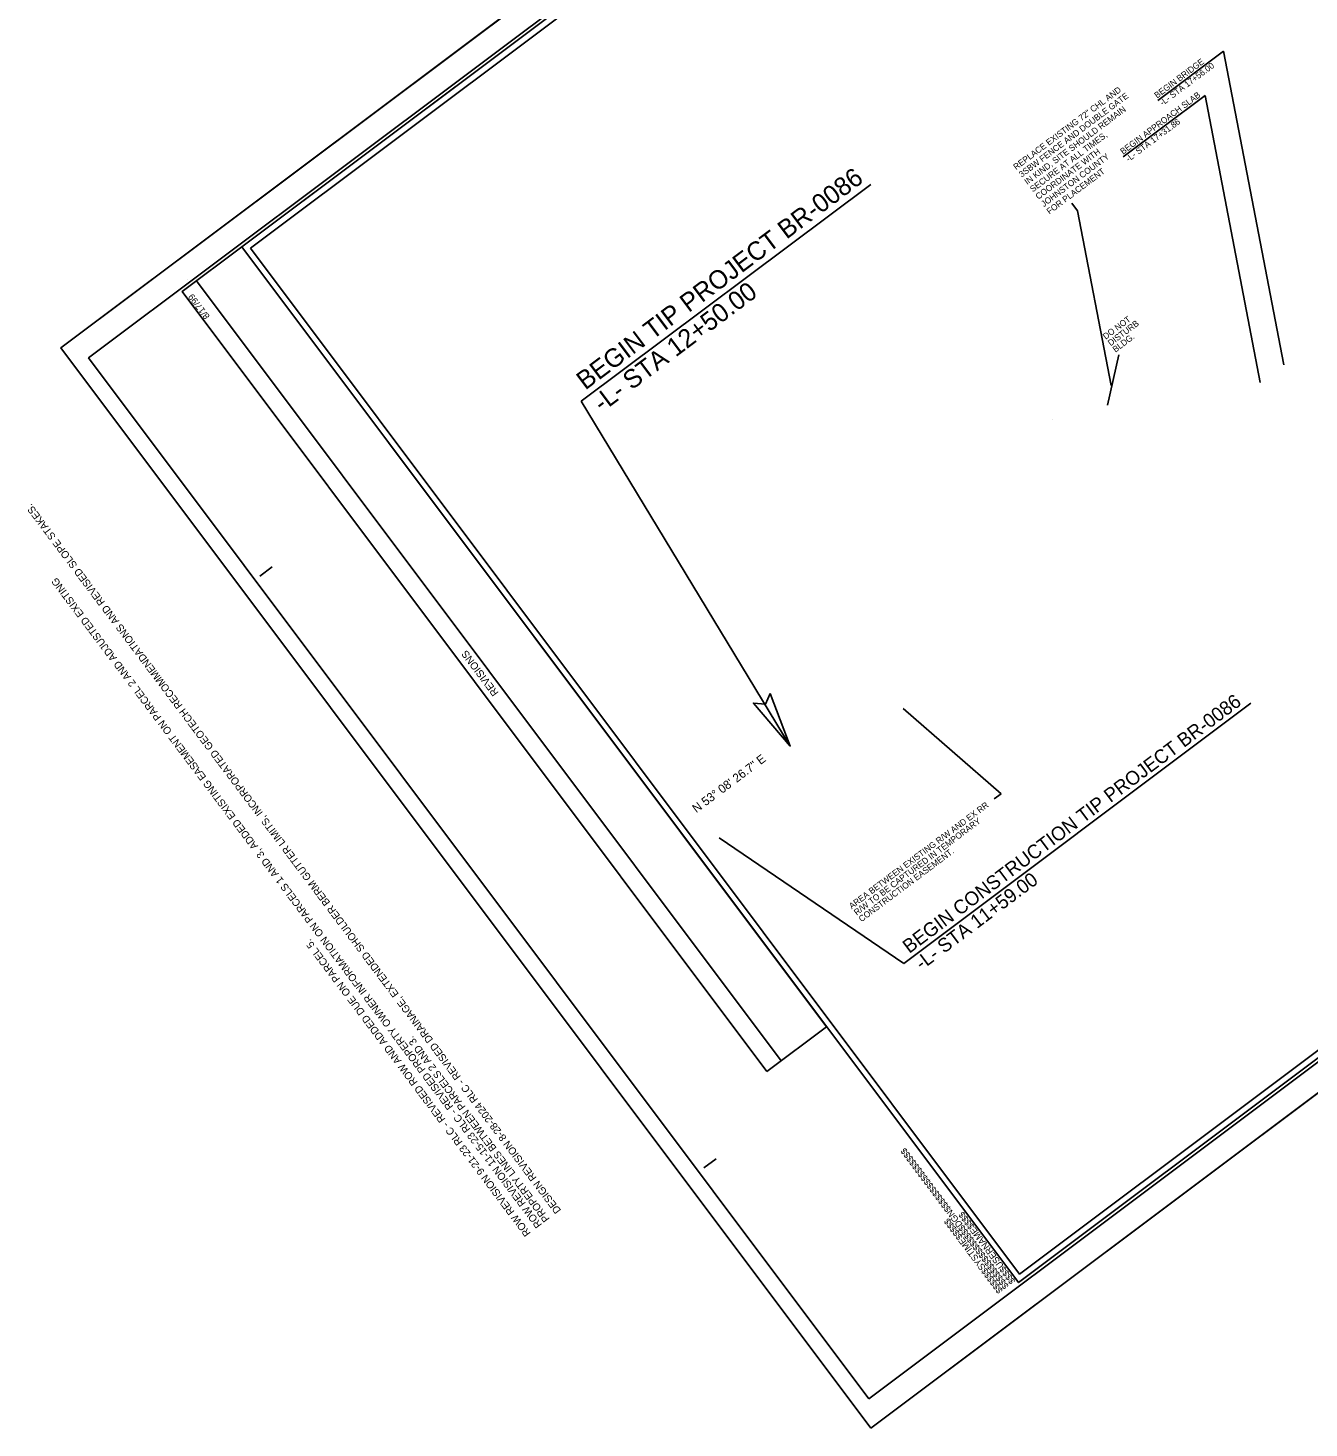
# Model space of a CAD drawing. Extents: x 2186558 to 2188589, y 629855 to 631741.
# Drawn here: x 2186558 to 2187597, y 629855 to 630990 of the extents above; entities that cross this region are included whole.
import ezdxf

# ---------------------------------------------------------------- set-up
doc = ezdxf.new("R2010")
doc.units = 0
for name, color, linetype in [('Prop Dimension', 7, 'Continuous'), ('Prop Dimension Text', 7, 'Continuous'), ('Prop Horizontal Alignment Direction Label', 7, 'Continuous'), ('Prop Terminator CELL', 7, 'Continuous'), ('Scratch_Level_0', 7, 'Continuous'), ('Scratch_Level_8', 7, 'Continuous'), ('Sheet Block Revision CELL', 7, 'Continuous'), ('Sheet Cutting Line CELL', 7, 'Continuous'), ('Sheet Plan CELL', 7, 'Continuous'), ('Sheet Plan Layout CELL', 7, 'Continuous'), ('Sheet Plot Border Inside CELL', 7, 'Continuous'), ('Sheet Plot Border Outside CELL', 7, 'Continuous')]:
    doc.layers.add(name, color=color, linetype=linetype)

msp = doc.modelspace()

# ---------------------------------------------------------------- linework, layer by layer
at = {"layer": 'Prop Dimension'}
for p, q in [((2187474.6, 630931.7), (2187527.8, 630971.6)), ((2187576.9, 630717.4), (2187527.8, 630971.6)), ((2187446.5, 630885.9), (2187513.1, 630935.8)), ((2187557.6, 630702.9), (2187513.1, 630935.8)), ((2187007, 630687.8), (2187241.7, 630863.7)), ((2187409.4, 630842.3), (2187404.8, 630848.5)), ((2187409.4, 630842.3), (2187436.7, 630700.5)), ((2187442.9, 630725.3), (2187433.8, 630684.5)), ((2187176.5, 630408.1), (2187007, 630687.8)), ((2187268.1, 630438.6), (2187347.4, 630369.5)), ((2187268.5, 630231.8), (2187549.9, 630442.8)), ((2187347.4, 630369.5), (2187341.9, 630365.4)), ((2187268.5, 630231.8), (2187118.9, 630333.8))]:
    msp.add_line(p, q, dxfattribs=at)
at = {"layer": 'Prop Terminator CELL'}
msp.add_lwpolyline([(2187160.3, 630450.8), (2187176.5, 630408.1), (2187146.6, 630443), (2187156.4, 630442.2)], close=True, dxfattribs=at)
at = {"layer": 'Scratch_Level_0'}
msp.add_line((2187388.8, 630672.8), (2187388.8, 630672.8), dxfattribs=at)
at = {"layer": 'Scratch_Level_8'}
msp.add_lwpolyline([(2186738.7, 630812), (2187930.9, 631705.8), (2188554.7, 630873.7), (2187362.5, 629979.9)], close=True, dxfattribs=at)
at = {"layer": 'Sheet Block Revision CELL'}
msp.add_line((2187169.2, 630152.8), (2186694.9, 630785.4), dxfattribs=at)
msp.add_lwpolyline([(2187157.6, 630144.1), (2186683.3, 630776.7), (2186731.7, 630813), (2187206, 630180.4)], close=True, dxfattribs=at)
at = {"layer": 'Sheet Cutting Line CELL'}
for p, q in [((2187932, 631741), (2186585, 630731.1)), ((2187241.8, 629855), (2188588.8, 630864.9)), ((2186585, 630731.1), (2187241.8, 629855))]:
    msp.add_line(p, q, dxfattribs=at)
at = {"layer": 'Sheet Plan CELL'}
for p, q in [((2186687.4, 630786.8), (2186687.4, 630786.8)), ((2186746.4, 630545.9), (2186756.4, 630553.4)), ((2187106.3, 630065.9), (2187116.3, 630073.3)), ((2187361.6, 629972.9), (2187361.6, 629972.9))]:
    msp.add_line(p, q, dxfattribs=at)
for points in [[(2187931.9, 631712.8), (2186731.7, 630813), (2187361.6, 629972.9), (2188561.7, 630872.7)], [(2187361.6, 629972.9), (2186731.7, 630813), (2187771.8, 631592.8), (2187861.8, 631472.8), (2188021.9, 631592.7), (2188561.7, 630872.7)]]:
    msp.add_lwpolyline(points, close=True, dxfattribs=at)
at = {"layer": 'Sheet Plan Layout CELL'}
msp.add_lwpolyline([(2186731.7, 630813), (2187361.6, 629972.9), (2188561.7, 630872.7), (2188058.7, 631543.6), (2187867.3, 631400.1), (2187740.4, 631569.3)], close=True, dxfattribs=at)
at = {"layer": 'Sheet Plot Border Inside CELL'}
msp.add_lwpolyline([(2187240.3, 629878.8), (2188573.2, 630878.2), (2187940.4, 631722.3), (2186607.4, 630722.9)], close=True, dxfattribs=at)
at = {"layer": 'Sheet Plot Border Outside CELL'}
msp.add_lwpolyline([(2187241.8, 629855), (2188588.8, 630864.9), (2187932, 631741), (2186585, 630731.1)], close=True, dxfattribs=at)

# ---------------------------------------------------------------- texts
at = {"layer": 'Prop Dimension Text'}
for s, height, p in [('BEGIN BRIDGE', 5, (2187474, 630933.2)), ('-L- STA 17+56.00', 5, (2187478.5, 630927.2)), ('REPLACE EXISTING 72" CHL AND', 5, (2187359.7, 630875.1)), ('3SBW FENCE AND DOUBLE GATE', 5, (2187364.2, 630869.1)), ('BEGIN APPROACH SLAB', 5, (2187446.4, 630887.7)), ('IN KIND, SITE SHOULD REMAIN', 5, (2187368.7, 630863.1)), ('-L- STA 17+31.86', 5, (2187450.9, 630881.7)), ('SECURE AT ALL TIMES,', 5, (2187373.2, 630857.1)), ('COORDINATE WITH', 5, (2187377.7, 630851.1)), ('JOHNSTON COUNTY', 5, (2187382.2, 630845.1)), ('BEGIN TIP PROJECT BR-0086', 15, (2187010.3, 630696.4)), ('FOR PLACEMENT', 5, (2187386.7, 630839.1)), ('-L- STA 12+50.00', 15, (2187023.8, 630678.4)), ('DO NOT', 5, (2187432.3, 630737.6)), ('DISTURB', 5, (2187436.3, 630732.3)), ('BLDG.', 5, (2187440.2, 630727.1)), ('BEGIN CONSTRUCTION TIP PROJECT BR-0086', 11.25, (2187273, 630239.5)), ('AREA BETWEEN EXISTING R/W AND EX RR ', 5, (2187226.4, 630275.7)), ('R/W TO BE CAPTURED IN TEMPORARY', 5, (2187230.4, 630270.5)), ('CONSTRUCTION EASEMENT.', 5, (2187234.3, 630265.2)), ('-L- STA 11+59.00', 11.25, (2187283.1, 630226))]:
    msp.add_text(s, height=height, rotation=36.8593, dxfattribs=at).set_placement(p)
at = {"layer": 'Prop Horizontal Alignment Direction Label'}
msp.add_text('N 53%%d 08\' 26.7" E', height=7, rotation=36.8593, dxfattribs=at).set_placement((2187100.3, 630353.6))
at = {"layer": 'Sheet Block Revision CELL'}
for s, p in [('DESIGN REVISION 8-28-2024 RLC - REVISED DRAINAGE, EXTENDED SHOULDER BERM GUTTER LIMITS, INCORPORATED GEOTECH RECOMMENDATIONS AND REVISED SLOPE STAKES.', (2186990.9, 630031.6)), ('ROW REVISION 11-15-23 RLC - REVISED PROPERTY OWNER INFORMATION ON PARCELS 1 AND 3, ADDED EXISTING EASEMENT ON PARCEL 2 AND ADJUSTED EXISTING', (2186975.4, 630019.9)), ('REVISIONS', (2186940.3, 630451.4)), ('ROW REVISION 9-21-23 RLC - REVISED ROW AND ADDED DUE ON PARCEL 5.', (2186966.3, 630013.1)), ('PROPERTY LINES BETWEEN PARCELS 2 AND 3. ', (2186981.7, 630024.7))]:
    msp.add_text(s, height=6, rotation=126.8593, dxfattribs=at).set_placement(p)
at = {"layer": 'Sheet Plan CELL'}
for s, p in [('8/17/99', (2186706, 630756.7)), ('$$$$$$$$$$$$$$$$DGN$$$$$$$$$$$$$$$$', (2187354, 629970.2)), ('$$$$USERNAME$$$$', (2187359.3, 629974.2)), ('$$$$$$SYSTIME$$$$$', (2187349.2, 629966.6))]:
    msp.add_text(s, height=5.25, rotation=126.8593, dxfattribs=at).set_placement(p)

doc.saveas('drawing.dxf')
